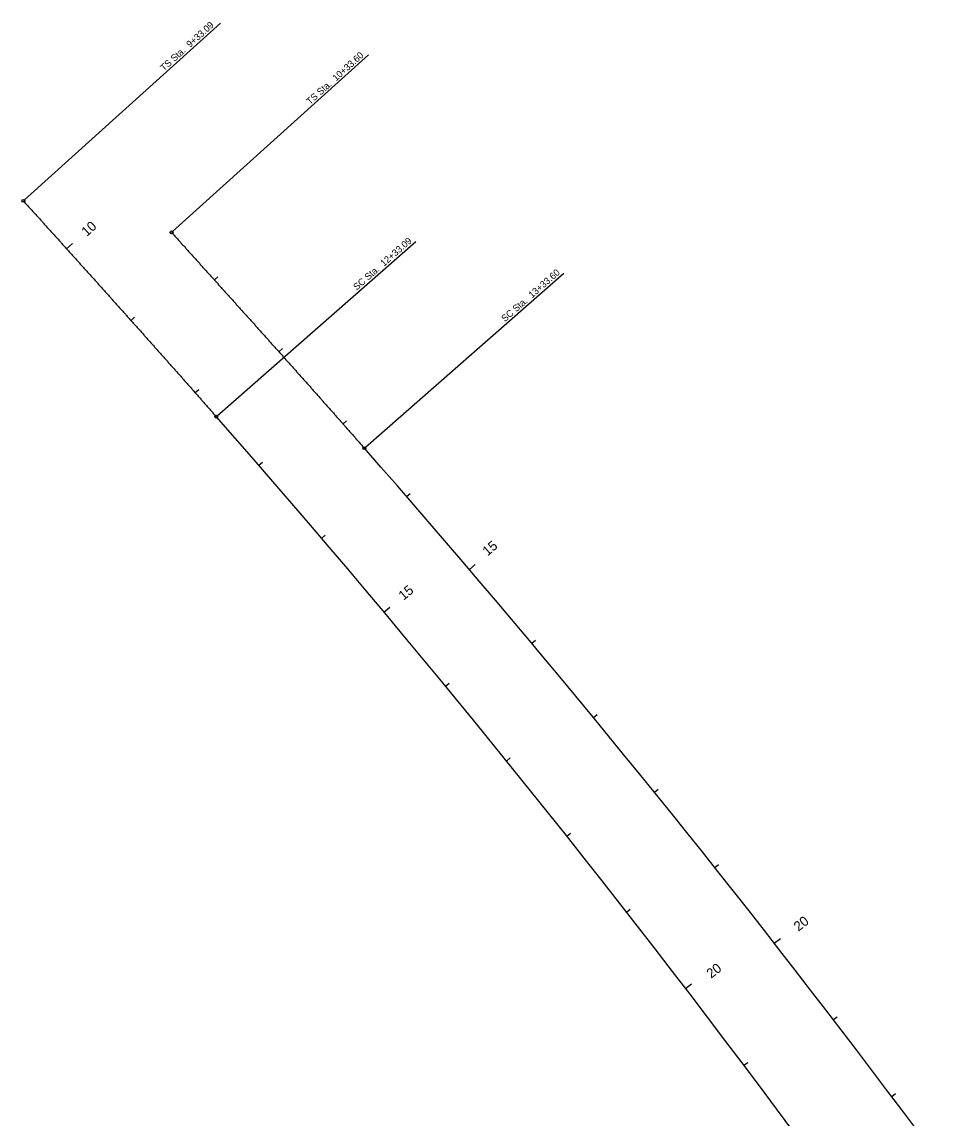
# Model space of a CAD drawing. Extents: x 1778969 to 1790720, y 807089 to 817794.
# Drawn here: x 1778969 to 1779937, y 816657 to 817794 of the extents above; entities that cross this region are included whole.
import ezdxf

# ---------------------------------------------------------------- set-up
doc = ezdxf.new("R2010")
doc.units = 0
for name, color, linetype in [('Prop Horizontal Alignment', 7, 'Continuous'), ('Prop Horizontal Alignment Station Label', 7, 'Continuous'), ('Prop Horizontal Alignment Tick Label', 7, 'Continuous'), ('Prop Horizontal Alignment Tick Large', 7, 'Continuous'), ('Prop Horizontal Alignment Tick Small', 7, 'Continuous')]:
    doc.layers.add(name, color=color, linetype=linetype)

msp = doc.modelspace()

# ---------------------------------------------------------------- linework, layer by layer
at = {"layer": 'Prop Horizontal Alignment'}
for centre, start in [((1770559.3, 809824.1), 31.75), ((1770559.3, 809824.1), 31.75), ((1770712.8, 809791.3), 32.96667)]:
    msp.add_arc(centre, 11459.2, start, 41.28333, dxfattribs=at)
for points in [[(1778970.4, 817608.3), (1778973.1, 817605.3), (1778975.8, 817602.3), (1778978.6, 817599.3), (1778981.3, 817596.3), (1778984, 817593.3), (1778986.7, 817590.3), (1778989.4, 817587.3), (1778992.1, 817584.3), (1778994.8, 817581.2), (1778997.6, 817578.2), (1779000.3, 817575.2), (1779003, 817572.2), (1779005.7, 817569.2), (1779008.4, 817566.2), (1779011.1, 817563.2), (1779013.8, 817560.2), (1779016.6, 817557.1), (1779019.3, 817554.1), (1779022, 817551.1), (1779024.7, 817548.1), (1779027.4, 817545.1), (1779030.1, 817542.1), (1779032.8, 817539.1), (1779035.5, 817536.1), (1779038.2, 817533), (1779041, 817530), (1779043.7, 817527), (1779046.4, 817524), (1779049.1, 817521), (1779051.8, 817518), (1779054.5, 817514.9), (1779057.2, 817511.9), (1779059.9, 817508.9), (1779062.6, 817505.9), (1779065.3, 817502.9), (1779068, 817499.8), (1779070.7, 817496.8), (1779073.4, 817493.8), (1779076.1, 817490.8), (1779078.8, 817487.8), (1779081.5, 817484.7), (1779084.2, 817481.7), (1779087, 817478.7), (1779089.7, 817475.7), (1779092.4, 817472.7), (1779095.1, 817469.6), (1779097.7, 817466.6), (1779100.4, 817463.6), (1779103.1, 817460.5), (1779105.8, 817457.5), (1779108.5, 817454.5), (1779111.2, 817451.5), (1779113.9, 817448.4), (1779116.6, 817445.4), (1779119.3, 817442.4), (1779122, 817439.3), (1779124.7, 817436.3), (1779127.4, 817433.3), (1779130.1, 817430.2), (1779132.8, 817427.2), (1779135.5, 817424.2), (1779138.1, 817421.1), (1779140.8, 817418.1), (1779143.5, 817415.1), (1779146.2, 817412), (1779148.9, 817409), (1779151.6, 817406), (1779154.2, 817402.9), (1779156.9, 817399.9), (1779159.6, 817396.8), (1779162.3, 817393.8), (1779165, 817390.7), (1779167.6, 817387.7), (1779170.3, 817384.7)], [(1779124, 817575.6), (1779126.7, 817572.6), (1779129.4, 817569.6), (1779132.1, 817566.5), (1779134.8, 817563.5), (1779137.6, 817560.5), (1779140.3, 817557.5), (1779143, 817554.5), (1779145.7, 817551.5), (1779148.4, 817548.5), (1779151.1, 817545.5), (1779153.8, 817542.5), (1779156.5, 817539.4), (1779159.3, 817536.4), (1779162, 817533.4), (1779164.7, 817530.4), (1779167.4, 817527.4), (1779170.1, 817524.4), (1779172.8, 817521.4), (1779175.5, 817518.4), (1779178.2, 817515.3), (1779181, 817512.3), (1779183.7, 817509.3), (1779186.4, 817506.3), (1779189.1, 817503.3), (1779191.8, 817500.3), (1779194.5, 817497.3), (1779197.2, 817494.2), (1779199.9, 817491.2), (1779202.6, 817488.2), (1779205.3, 817485.2), (1779208.1, 817482.2), (1779210.8, 817479.2), (1779213.5, 817476.1), (1779216.2, 817473.1), (1779218.9, 817470.1), (1779221.6, 817467.1), (1779224.3, 817464.1), (1779227, 817461), (1779229.7, 817458), (1779232.4, 817455), (1779235.1, 817452), (1779237.8, 817449), (1779240.5, 817445.9), (1779243.2, 817442.9), (1779245.9, 817439.9), (1779248.6, 817436.9), (1779251.3, 817433.8), (1779254, 817430.8), (1779256.7, 817427.8), (1779259.4, 817424.8), (1779262.1, 817421.7), (1779264.8, 817418.7), (1779267.5, 817415.7), (1779270.2, 817412.6), (1779272.9, 817409.6), (1779275.6, 817406.6), (1779278.3, 817403.5), (1779280.9, 817400.5), (1779283.6, 817397.5), (1779286.3, 817394.4), (1779289, 817391.4), (1779291.7, 817388.4), (1779294.4, 817385.3), (1779297.1, 817382.3), (1779299.8, 817379.3), (1779302.4, 817376.2), (1779305.1, 817373.2), (1779307.8, 817370.1), (1779310.5, 817367.1), (1779313.2, 817364.1), (1779315.8, 817361), (1779318.5, 817358), (1779321.2, 817354.9), (1779323.9, 817351.9)]]:
    msp.add_spline(points, degree=3, dxfattribs=at)
at = {"layer": 'Prop Horizontal Alignment Station Label'}
for p, q in [((1778971.5, 817609.4), (1779174.7, 817792.5)), ((1779125.1, 817576.6), (1779328.2, 817759.7)), ((1779171.4, 817385.6), (1779377, 817566.1)), ((1779325, 817352.9), (1779530.5, 817533.3))]:
    msp.add_line(p, q, dxfattribs=at)
for centre in [(1778970.4, 817608.3), (1779124, 817575.6), (1779170.3, 817384.7), (1779323.9, 817351.9)]:
    msp.add_circle(centre, 1.5, dxfattribs=at)
at = {"layer": 'Prop Horizontal Alignment Tick Large'}
for p, q in [((1779015.2, 817558.6), (1779021.2, 817564)), ((1779432.7, 817226), (1779438.8, 817231.2)), ((1779344.1, 817182), (1779350.2, 817187.2)), ((1779748.7, 816838.6), (1779755.1, 816843.5)), ((1779656.7, 816791.9), (1779663, 816796.7))]:
    msp.add_line(p, q, dxfattribs=at)
at = {"layer": 'Prop Horizontal Alignment Tick Small'}
for p, q in [((1779168.4, 817526.3), (1779172.1, 817529.6)), ((1779082, 817484.2), (1779085.7, 817487.6)), ((1779235.2, 817451.8), (1779239, 817455.2)), ((1779148.4, 817409.5), (1779152.2, 817412.8)), ((1779301.7, 817377.1), (1779305.4, 817380.4)), ((1779214.3, 817334.2), (1779218.1, 817337.5)), ((1779367.5, 817301.9), (1779371.3, 817305.1)), ((1779279.5, 817258.4), (1779283.3, 817261.7)), ((1779497.3, 817149.7), (1779501.1, 817152.9)), ((1779407.9, 817105.1), (1779411.8, 817108.3)), ((1779561.2, 817072.7), (1779565, 817075.9)), ((1779471.1, 817027.6), (1779475, 817030.8)), ((1779624.4, 816995.2), (1779628.3, 816998.4)), ((1779533.7, 816949.6), (1779537.6, 816952.7)), ((1779686.9, 816917.2), (1779690.8, 816920.3)), ((1779595.5, 816871), (1779599.4, 816874.1)), ((1779809.9, 816759.5), (1779813.9, 816762.5)), ((1779717.1, 816712.2), (1779721.1, 816715.2)), ((1779870.4, 816679.8), (1779874.4, 816682.8))]:
    msp.add_line(p, q, dxfattribs=at)

# ---------------------------------------------------------------- texts
at = {"layer": 'Prop Horizontal Alignment Station Label'}
for s, rotation, p in [('TS Sta.  9+33.09', 42.0333, (1779116.1, 817742.4)), ('TS Sta.  10+33.60', 42.0333, (1779267.5, 817707.6)), ('SC Sta.  12+33.09', 41.2833, (1779316, 817515.2)), ('SC Sta.  13+33.60', 41.2833, (1779469.5, 817482.4))]:
    msp.add_text(s, height=7, rotation=rotation, dxfattribs=at).set_placement(p)
at = {"layer": 'Prop Horizontal Alignment Tick Label'}
for s, rotation, p in [('10', 41.996, (1779036.1, 817570.8)), ('15', 40.4513, (1779451.5, 817239.6)), ('15', 39.9488, (1779364.4, 817193.6)), ('20', 37.9513, (1779773.7, 816850.6)), ('20', 37.4488, (1779683.2, 816801.8))]:
    msp.add_text(s, height=10, rotation=rotation, dxfattribs=at).set_placement(p)

doc.saveas('drawing.dxf')
